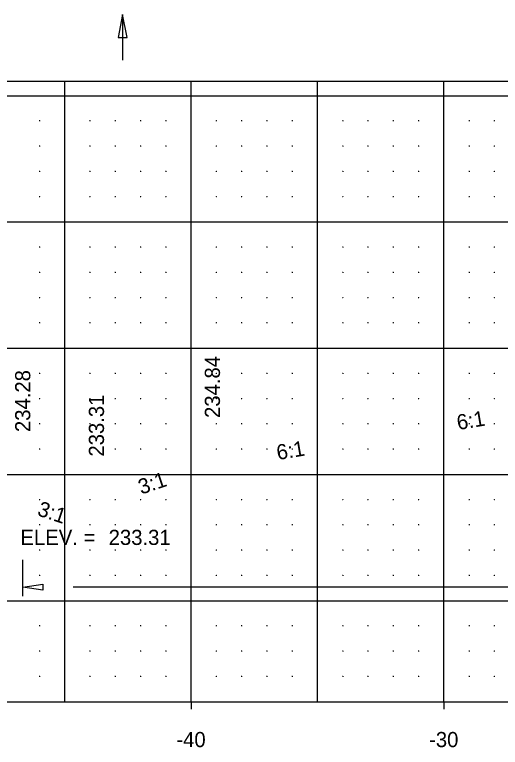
# Model space of a CAD drawing. Extents: x -80 to 80, y 222 to 253.
# Drawn here: x -46.98 to -27.76, y 224.19 to 253.21 of the extents above; entities that cross this region are included whole.
import ezdxf

# ---------------------------------------------------------------- set-up
doc = ezdxf.new("R2010")
doc.units = 0
for name, color, linetype in [('DSN_DRFT_XS Border Grid', 7, 'Continuous'), ('DSN_DRFT_XS Grid Annotations', 7, 'Continuous'), ('DSN_DRFT_XS Grid Major', 7, 'Continuous'), ('DSN_DRFT_XS Grid Minor', 7, 'Continuous'), ('DSN_DRFT_XS MOT STG Annotations', 7, 'Continuous'), ('DSN_RDWY_Flow Arrow', 7, 'Continuous'), ('DSN_RDWY_XS Annotation', 7, 'Continuous')]:
    doc.layers.add(name, color=color, linetype=linetype)

msp = doc.modelspace()

# ---------------------------------------------------------------- linework, layer by layer
at = {"layer": 'DSN_DRFT_XS Border Grid'}
for p, q in [((-77.5, 250.573), (77.5, 250.573)), ((-77.5, 226), (77.5, 226))]:
    msp.add_line(p, q, dxfattribs=at)
at = {"layer": 'DSN_DRFT_XS Grid Major'}
for p, q in [((-45, 226), (-45, 250.573)), ((-40, 226), (-40, 250.573)), ((-35, 226), (-35, 250.573)), ((-30, 226), (-30, 250.573)), ((-77.5, 250), (77.5, 250)), ((-77.5, 245), (77.5, 245)), ((-77.5, 240), (77.5, 240)), ((-77.5, 235), (77.5, 235)), ((-77.5, 230), (77.5, 230)), ((-40, 226), (-40, 225.7)), ((-30, 226), (-30, 225.7))]:
    msp.add_line(p, q, dxfattribs=at)
at = {"layer": 'DSN_DRFT_XS Grid Minor'}
for p, q in [((-45.988, 249), (-46.012, 249)), ((-46, 249.012), (-46, 248.988)), ((-43.988, 249), (-44.012, 249)), ((-44, 249.012), (-44, 248.988)), ((-42.988, 249), (-43.012, 249)), ((-43, 249.012), (-43, 248.988)), ((-41.988, 249), (-42.012, 249)), ((-42, 249.012), (-42, 248.988)), ((-40.988, 249), (-41.012, 249)), ((-41, 249.012), (-41, 248.988)), ((-38.988, 249), (-39.012, 249)), ((-39, 249.012), (-39, 248.988)), ((-37.988, 249), (-38.012, 249)), ((-38, 249.012), (-38, 248.988)), ((-36.988, 249), (-37.012, 249)), ((-37, 249.012), (-37, 248.988)), ((-35.988, 249), (-36.012, 249)), ((-36, 249.012), (-36, 248.988)), ((-33.988, 249), (-34.012, 249)), ((-34, 249.012), (-34, 248.988)), ((-32.988, 249), (-33.012, 249)), ((-33, 249.012), (-33, 248.988)), ((-31.988, 249), (-32.012, 249)), ((-32, 249.012), (-32, 248.988)), ((-30.988, 249), (-31.012, 249)), ((-31, 249.012), (-31, 248.988)), ((-28.988, 249), (-29.012, 249)), ((-29, 249.012), (-29, 248.988)), ((-27.988, 249), (-28.012, 249)), ((-28, 249.012), (-28, 248.988)), ((-45.988, 248), (-46.012, 248)), ((-46, 248.012), (-46, 247.988)), ((-43.988, 248), (-44.012, 248)), ((-44, 248.012), (-44, 247.988)), ((-42.988, 248), (-43.012, 248)), ((-43, 248.012), (-43, 247.988)), ((-41.988, 248), (-42.012, 248)), ((-42, 248.012), (-42, 247.988)), ((-40.988, 248), (-41.012, 248)), ((-41, 248.012), (-41, 247.988)), ((-38.988, 248), (-39.012, 248)), ((-39, 248.012), (-39, 247.988)), ((-37.988, 248), (-38.012, 248)), ((-38, 248.012), (-38, 247.988)), ((-36.988, 248), (-37.012, 248)), ((-37, 248.012), (-37, 247.988)), ((-35.988, 248), (-36.012, 248)), ((-36, 248.012), (-36, 247.988)), ((-33.988, 248), (-34.012, 248)), ((-34, 248.012), (-34, 247.988)), ((-32.988, 248), (-33.012, 248)), ((-33, 248.012), (-33, 247.988)), ((-31.988, 248), (-32.012, 248)), ((-32, 248.012), (-32, 247.988)), ((-30.988, 248), (-31.012, 248)), ((-31, 248.012), (-31, 247.988)), ((-28.988, 248), (-29.012, 248)), ((-29, 248.012), (-29, 247.988)), ((-27.988, 248), (-28.012, 248)), ((-28, 248.012), (-28, 247.988)), ((-45.988, 247), (-46.012, 247)), ((-46, 247.012), (-46, 246.988)), ((-43.988, 247), (-44.012, 247)), ((-44, 247.012), (-44, 246.988)), ((-42.988, 247), (-43.012, 247)), ((-43, 247.012), (-43, 246.988)), ((-41.988, 247), (-42.012, 247)), ((-42, 247.012), (-42, 246.988)), ((-40.988, 247), (-41.012, 247)), ((-41, 247.012), (-41, 246.988)), ((-38.988, 247), (-39.012, 247)), ((-39, 247.012), (-39, 246.988)), ((-37.988, 247), (-38.012, 247)), ((-38, 247.012), (-38, 246.988)), ((-36.988, 247), (-37.012, 247)), ((-37, 247.012), (-37, 246.988)), ((-35.988, 247), (-36.012, 247)), ((-36, 247.012), (-36, 246.988)), ((-33.988, 247), (-34.012, 247)), ((-34, 247.012), (-34, 246.988)), ((-32.988, 247), (-33.012, 247)), ((-33, 247.012), (-33, 246.988)), ((-31.988, 247), (-32.012, 247)), ((-32, 247.012), (-32, 246.988)), ((-30.988, 247), (-31.012, 247)), ((-31, 247.012), (-31, 246.988)), ((-28.988, 247), (-29.012, 247)), ((-29, 247.012), (-29, 246.988)), ((-27.988, 247), (-28.012, 247)), ((-28, 247.012), (-28, 246.988)), ((-45.988, 246), (-46.012, 246)), ((-46, 246.012), (-46, 245.988)), ((-43.988, 246), (-44.012, 246)), ((-44, 246.012), (-44, 245.988)), ((-42.988, 246), (-43.012, 246)), ((-43, 246.012), (-43, 245.988)), ((-41.988, 246), (-42.012, 246)), ((-42, 246.012), (-42, 245.988)), ((-40.988, 246), (-41.012, 246)), ((-41, 246.012), (-41, 245.988)), ((-38.988, 246), (-39.012, 246)), ((-39, 246.012), (-39, 245.988)), ((-37.988, 246), (-38.012, 246)), ((-38, 246.012), (-38, 245.988)), ((-36.988, 246), (-37.012, 246)), ((-37, 246.012), (-37, 245.988)), ((-35.988, 246), (-36.012, 246)), ((-36, 246.012), (-36, 245.988)), ((-33.988, 246), (-34.012, 246)), ((-34, 246.012), (-34, 245.988)), ((-32.988, 246), (-33.012, 246)), ((-33, 246.012), (-33, 245.988)), ((-31.988, 246), (-32.012, 246)), ((-32, 246.012), (-32, 245.988)), ((-30.988, 246), (-31.012, 246)), ((-31, 246.012), (-31, 245.988)), ((-28.988, 246), (-29.012, 246)), ((-29, 246.012), (-29, 245.988)), ((-27.988, 246), (-28.012, 246)), ((-28, 246.012), (-28, 245.988)), ((-45.988, 244), (-46.012, 244)), ((-46, 244.012), (-46, 243.988)), ((-43.988, 244), (-44.012, 244)), ((-44, 244.012), (-44, 243.988)), ((-42.988, 244), (-43.012, 244)), ((-43, 244.012), (-43, 243.988)), ((-41.988, 244), (-42.012, 244)), ((-42, 244.012), (-42, 243.988)), ((-40.988, 244), (-41.012, 244)), ((-41, 244.012), (-41, 243.988)), ((-38.988, 244), (-39.012, 244)), ((-39, 244.012), (-39, 243.988)), ((-37.988, 244), (-38.012, 244)), ((-38, 244.012), (-38, 243.988)), ((-36.988, 244), (-37.012, 244)), ((-37, 244.012), (-37, 243.988)), ((-35.988, 244), (-36.012, 244)), ((-36, 244.012), (-36, 243.988)), ((-33.988, 244), (-34.012, 244)), ((-34, 244.012), (-34, 243.988)), ((-32.988, 244), (-33.012, 244)), ((-33, 244.012), (-33, 243.988)), ((-31.988, 244), (-32.012, 244)), ((-32, 244.012), (-32, 243.988)), ((-30.988, 244), (-31.012, 244)), ((-31, 244.012), (-31, 243.988)), ((-28.988, 244), (-29.012, 244)), ((-29, 244.012), (-29, 243.988)), ((-27.988, 244), (-28.012, 244)), ((-28, 244.012), (-28, 243.988)), ((-45.988, 243), (-46.012, 243)), ((-46, 243.012), (-46, 242.988)), ((-43.988, 243), (-44.012, 243)), ((-44, 243.012), (-44, 242.988)), ((-42.988, 243), (-43.012, 243)), ((-43, 243.012), (-43, 242.988)), ((-41.988, 243), (-42.012, 243)), ((-42, 243.012), (-42, 242.988)), ((-40.988, 243), (-41.012, 243)), ((-41, 243.012), (-41, 242.988)), ((-38.988, 243), (-39.012, 243)), ((-39, 243.012), (-39, 242.988)), ((-37.988, 243), (-38.012, 243)), ((-38, 243.012), (-38, 242.988)), ((-36.988, 243), (-37.012, 243)), ((-37, 243.012), (-37, 242.988)), ((-35.988, 243), (-36.012, 243)), ((-36, 243.012), (-36, 242.988)), ((-33.988, 243), (-34.012, 243)), ((-34, 243.012), (-34, 242.988)), ((-32.988, 243), (-33.012, 243)), ((-33, 243.012), (-33, 242.988)), ((-31.988, 243), (-32.012, 243)), ((-32, 243.012), (-32, 242.988)), ((-30.988, 243), (-31.012, 243)), ((-31, 243.012), (-31, 242.988)), ((-28.988, 243), (-29.012, 243)), ((-29, 243.012), (-29, 242.988)), ((-27.988, 243), (-28.012, 243)), ((-28, 243.012), (-28, 242.988)), ((-46, 242.012), (-46, 241.988)), ((-44, 242.012), (-44, 241.988)), ((-43, 242.012), (-43, 241.988)), ((-42, 242.012), (-42, 241.988)), ((-41, 242.012), (-41, 241.988)), ((-39, 242.012), (-39, 241.988)), ((-38, 242.012), (-38, 241.988)), ((-37, 242.012), (-37, 241.988)), ((-36, 242.012), (-36, 241.988)), ((-34, 242.012), (-34, 241.988)), ((-33, 242.012), (-33, 241.988)), ((-32, 242.012), (-32, 241.988)), ((-31, 242.012), (-31, 241.988)), ((-29, 242.012), (-29, 241.988)), ((-28, 242.012), (-28, 241.988)), ((-45.988, 242), (-46.012, 242)), ((-43.988, 242), (-44.012, 242)), ((-42.988, 242), (-43.012, 242)), ((-41.988, 242), (-42.012, 242)), ((-40.988, 242), (-41.012, 242)), ((-38.988, 242), (-39.012, 242)), ((-37.988, 242), (-38.012, 242)), ((-36.988, 242), (-37.012, 242)), ((-35.988, 242), (-36.012, 242)), ((-33.988, 242), (-34.012, 242)), ((-32.988, 242), (-33.012, 242)), ((-31.988, 242), (-32.012, 242)), ((-30.988, 242), (-31.012, 242)), ((-28.988, 242), (-29.012, 242)), ((-27.988, 242), (-28.012, 242)), ((-45.988, 241), (-46.012, 241)), ((-46, 241.012), (-46, 240.988)), ((-43.988, 241), (-44.012, 241)), ((-44, 241.012), (-44, 240.988)), ((-42.988, 241), (-43.012, 241)), ((-43, 241.012), (-43, 240.988)), ((-41.988, 241), (-42.012, 241)), ((-42, 241.012), (-42, 240.988)), ((-40.988, 241), (-41.012, 241)), ((-41, 241.012), (-41, 240.988)), ((-38.988, 241), (-39.012, 241)), ((-39, 241.012), (-39, 240.988)), ((-37.988, 241), (-38.012, 241)), ((-38, 241.012), (-38, 240.988)), ((-36.988, 241), (-37.012, 241)), ((-37, 241.012), (-37, 240.988)), ((-35.988, 241), (-36.012, 241)), ((-36, 241.012), (-36, 240.988)), ((-33.988, 241), (-34.012, 241)), ((-34, 241.012), (-34, 240.988)), ((-32.988, 241), (-33.012, 241)), ((-33, 241.012), (-33, 240.988)), ((-31.988, 241), (-32.012, 241)), ((-32, 241.012), (-32, 240.988)), ((-30.988, 241), (-31.012, 241)), ((-31, 241.012), (-31, 240.988)), ((-28.988, 241), (-29.012, 241)), ((-29, 241.012), (-29, 240.988)), ((-27.988, 241), (-28.012, 241)), ((-28, 241.012), (-28, 240.988)), ((-45.988, 239), (-46.012, 239)), ((-46, 239.012), (-46, 238.988)), ((-43.988, 239), (-44.012, 239)), ((-44, 239.012), (-44, 238.988)), ((-42.988, 239), (-43.012, 239)), ((-43, 239.012), (-43, 238.988)), ((-41.988, 239), (-42.012, 239)), ((-42, 239.012), (-42, 238.988)), ((-40.988, 239), (-41.012, 239)), ((-41, 239.012), (-41, 238.988)), ((-38.988, 239), (-39.012, 239)), ((-39, 239.012), (-39, 238.988)), ((-37.988, 239), (-38.012, 239)), ((-38, 239.012), (-38, 238.988)), ((-36.988, 239), (-37.012, 239)), ((-37, 239.012), (-37, 238.988)), ((-35.988, 239), (-36.012, 239)), ((-36, 239.012), (-36, 238.988)), ((-33.988, 239), (-34.012, 239)), ((-34, 239.012), (-34, 238.988)), ((-32.988, 239), (-33.012, 239)), ((-33, 239.012), (-33, 238.988)), ((-31.988, 239), (-32.012, 239)), ((-32, 239.012), (-32, 238.988)), ((-30.988, 239), (-31.012, 239)), ((-31, 239.012), (-31, 238.988)), ((-28.988, 239), (-29.012, 239)), ((-29, 239.012), (-29, 238.988)), ((-27.988, 239), (-28.012, 239)), ((-28, 239.012), (-28, 238.988)), ((-45.988, 238), (-46.012, 238)), ((-46, 238.012), (-46, 237.988)), ((-43.988, 238), (-44.012, 238)), ((-44, 238.012), (-44, 237.988)), ((-42.988, 238), (-43.012, 238)), ((-43, 238.012), (-43, 237.988)), ((-41.988, 238), (-42.012, 238)), ((-42, 238.012), (-42, 237.988)), ((-40.988, 238), (-41.012, 238)), ((-41, 238.012), (-41, 237.988)), ((-38.988, 238), (-39.012, 238)), ((-39, 238.012), (-39, 237.988)), ((-37.988, 238), (-38.012, 238)), ((-38, 238.012), (-38, 237.988)), ((-36.988, 238), (-37.012, 238)), ((-37, 238.012), (-37, 237.988)), ((-35.988, 238), (-36.012, 238)), ((-36, 238.012), (-36, 237.988)), ((-33.988, 238), (-34.012, 238)), ((-34, 238.012), (-34, 237.988)), ((-32.988, 238), (-33.012, 238)), ((-33, 238.012), (-33, 237.988)), ((-31.988, 238), (-32.012, 238)), ((-32, 238.012), (-32, 237.988)), ((-30.988, 238), (-31.012, 238)), ((-31, 238.012), (-31, 237.988)), ((-28.988, 238), (-29.012, 238)), ((-29, 238.012), (-29, 237.988)), ((-27.988, 238), (-28.012, 238)), ((-28, 238.012), (-28, 237.988)), ((-45.988, 237), (-46.012, 237)), ((-46, 237.012), (-46, 236.988)), ((-43.988, 237), (-44.012, 237)), ((-44, 237.012), (-44, 236.988)), ((-42.988, 237), (-43.012, 237)), ((-43, 237.012), (-43, 236.988)), ((-41.988, 237), (-42.012, 237)), ((-42, 237.012), (-42, 236.988)), ((-40.988, 237), (-41.012, 237)), ((-41, 237.012), (-41, 236.988)), ((-38.988, 237), (-39.012, 237)), ((-39, 237.012), (-39, 236.988)), ((-37.988, 237), (-38.012, 237)), ((-38, 237.012), (-38, 236.988)), ((-36.988, 237), (-37.012, 237)), ((-37, 237.012), (-37, 236.988)), ((-35.988, 237), (-36.012, 237)), ((-36, 237.012), (-36, 236.988)), ((-33.988, 237), (-34.012, 237)), ((-34, 237.012), (-34, 236.988)), ((-32.988, 237), (-33.012, 237)), ((-33, 237.012), (-33, 236.988)), ((-31.988, 237), (-32.012, 237)), ((-32, 237.012), (-32, 236.988)), ((-30.988, 237), (-31.012, 237)), ((-31, 237.012), (-31, 236.988)), ((-28.988, 237), (-29.012, 237)), ((-29, 237.012), (-29, 236.988)), ((-27.988, 237), (-28.012, 237)), ((-28, 237.012), (-28, 236.988)), ((-45.988, 236), (-46.012, 236)), ((-46, 236.012), (-46, 235.988)), ((-43.988, 236), (-44.012, 236)), ((-44, 236.012), (-44, 235.988)), ((-42.988, 236), (-43.012, 236)), ((-43, 236.012), (-43, 235.988)), ((-41.988, 236), (-42.012, 236)), ((-42, 236.012), (-42, 235.988)), ((-40.988, 236), (-41.012, 236)), ((-41, 236.012), (-41, 235.988)), ((-38.988, 236), (-39.012, 236)), ((-39, 236.012), (-39, 235.988)), ((-37.988, 236), (-38.012, 236)), ((-38, 236.012), (-38, 235.988)), ((-36.988, 236), (-37.012, 236)), ((-37, 236.012), (-37, 235.988)), ((-35.988, 236), (-36.012, 236)), ((-36, 236.012), (-36, 235.988)), ((-33.988, 236), (-34.012, 236)), ((-34, 236.012), (-34, 235.988)), ((-32.988, 236), (-33.012, 236)), ((-33, 236.012), (-33, 235.988)), ((-31.988, 236), (-32.012, 236)), ((-32, 236.012), (-32, 235.988)), ((-30.988, 236), (-31.012, 236)), ((-31, 236.012), (-31, 235.988)), ((-28.988, 236), (-29.012, 236)), ((-29, 236.012), (-29, 235.988)), ((-27.988, 236), (-28.012, 236)), ((-28, 236.012), (-28, 235.988)), ((-45.988, 234), (-46.012, 234)), ((-46, 234.012), (-46, 233.988)), ((-43.988, 234), (-44.012, 234)), ((-44, 234.012), (-44, 233.988)), ((-42.988, 234), (-43.012, 234)), ((-43, 234.012), (-43, 233.988)), ((-41.988, 234), (-42.012, 234)), ((-42, 234.012), (-42, 233.988)), ((-40.988, 234), (-41.012, 234)), ((-41, 234.012), (-41, 233.988)), ((-38.988, 234), (-39.012, 234)), ((-39, 234.012), (-39, 233.988)), ((-37.988, 234), (-38.012, 234)), ((-38, 234.012), (-38, 233.988)), ((-36.988, 234), (-37.012, 234)), ((-37, 234.012), (-37, 233.988)), ((-35.988, 234), (-36.012, 234)), ((-36, 234.012), (-36, 233.988)), ((-33.988, 234), (-34.012, 234)), ((-34, 234.012), (-34, 233.988)), ((-32.988, 234), (-33.012, 234)), ((-33, 234.012), (-33, 233.988)), ((-31.988, 234), (-32.012, 234)), ((-32, 234.012), (-32, 233.988)), ((-30.988, 234), (-31.012, 234)), ((-31, 234.012), (-31, 233.988)), ((-28.988, 234), (-29.012, 234)), ((-29, 234.012), (-29, 233.988)), ((-27.988, 234), (-28.012, 234)), ((-28, 234.012), (-28, 233.988)), ((-46, 233.012), (-46, 232.988)), ((-44, 233.012), (-44, 232.988)), ((-43, 233.012), (-43, 232.988)), ((-42, 233.012), (-42, 232.988)), ((-41, 233.012), (-41, 232.988)), ((-39, 233.012), (-39, 232.988)), ((-38, 233.012), (-38, 232.988)), ((-37, 233.012), (-37, 232.988)), ((-36, 233.012), (-36, 232.988)), ((-34, 233.012), (-34, 232.988)), ((-33, 233.012), (-33, 232.988)), ((-32, 233.012), (-32, 232.988)), ((-31, 233.012), (-31, 232.988)), ((-29, 233.012), (-29, 232.988)), ((-28, 233.012), (-28, 232.988)), ((-45.988, 233), (-46.012, 233)), ((-43.988, 233), (-44.012, 233)), ((-42.988, 233), (-43.012, 233)), ((-41.988, 233), (-42.012, 233)), ((-40.988, 233), (-41.012, 233)), ((-38.988, 233), (-39.012, 233)), ((-37.988, 233), (-38.012, 233)), ((-36.988, 233), (-37.012, 233)), ((-35.988, 233), (-36.012, 233)), ((-33.988, 233), (-34.012, 233)), ((-32.988, 233), (-33.012, 233)), ((-31.988, 233), (-32.012, 233)), ((-30.988, 233), (-31.012, 233)), ((-28.988, 233), (-29.012, 233)), ((-27.988, 233), (-28.012, 233)), ((-45.988, 232), (-46.012, 232)), ((-46, 232.012), (-46, 231.988)), ((-43.988, 232), (-44.012, 232)), ((-44, 232.012), (-44, 231.988)), ((-42.988, 232), (-43.012, 232)), ((-43, 232.012), (-43, 231.988)), ((-41.988, 232), (-42.012, 232)), ((-42, 232.012), (-42, 231.988)), ((-40.988, 232), (-41.012, 232)), ((-41, 232.012), (-41, 231.988)), ((-38.988, 232), (-39.012, 232)), ((-39, 232.012), (-39, 231.988)), ((-37.988, 232), (-38.012, 232)), ((-38, 232.012), (-38, 231.988)), ((-36.988, 232), (-37.012, 232)), ((-37, 232.012), (-37, 231.988)), ((-35.988, 232), (-36.012, 232)), ((-36, 232.012), (-36, 231.988)), ((-33.988, 232), (-34.012, 232)), ((-34, 232.012), (-34, 231.988)), ((-32.988, 232), (-33.012, 232)), ((-33, 232.012), (-33, 231.988)), ((-31.988, 232), (-32.012, 232)), ((-32, 232.012), (-32, 231.988)), ((-30.988, 232), (-31.012, 232)), ((-31, 232.012), (-31, 231.988)), ((-28.988, 232), (-29.012, 232)), ((-29, 232.012), (-29, 231.988)), ((-27.988, 232), (-28.012, 232)), ((-28, 232.012), (-28, 231.988)), ((-45.988, 231), (-46.012, 231)), ((-46, 231.012), (-46, 230.988)), ((-43.988, 231), (-44.012, 231)), ((-44, 231.012), (-44, 230.988)), ((-42.988, 231), (-43.012, 231)), ((-43, 231.012), (-43, 230.988)), ((-41.988, 231), (-42.012, 231)), ((-42, 231.012), (-42, 230.988)), ((-40.988, 231), (-41.012, 231)), ((-41, 231.012), (-41, 230.988)), ((-38.988, 231), (-39.012, 231)), ((-39, 231.012), (-39, 230.988)), ((-37.988, 231), (-38.012, 231)), ((-38, 231.012), (-38, 230.988)), ((-36.988, 231), (-37.012, 231)), ((-37, 231.012), (-37, 230.988)), ((-35.988, 231), (-36.012, 231)), ((-36, 231.012), (-36, 230.988)), ((-33.988, 231), (-34.012, 231)), ((-34, 231.012), (-34, 230.988)), ((-32.988, 231), (-33.012, 231)), ((-33, 231.012), (-33, 230.988)), ((-31.988, 231), (-32.012, 231)), ((-32, 231.012), (-32, 230.988)), ((-30.988, 231), (-31.012, 231)), ((-31, 231.012), (-31, 230.988)), ((-28.988, 231), (-29.012, 231)), ((-29, 231.012), (-29, 230.988)), ((-27.988, 231), (-28.012, 231)), ((-28, 231.012), (-28, 230.988)), ((-45.988, 229), (-46.012, 229)), ((-46, 229.012), (-46, 228.988)), ((-43.988, 229), (-44.012, 229)), ((-44, 229.012), (-44, 228.988)), ((-42.988, 229), (-43.012, 229)), ((-43, 229.012), (-43, 228.988)), ((-41.988, 229), (-42.012, 229)), ((-42, 229.012), (-42, 228.988)), ((-40.988, 229), (-41.012, 229)), ((-41, 229.012), (-41, 228.988)), ((-38.988, 229), (-39.012, 229)), ((-39, 229.012), (-39, 228.988)), ((-37.988, 229), (-38.012, 229)), ((-38, 229.012), (-38, 228.988)), ((-36.988, 229), (-37.012, 229)), ((-37, 229.012), (-37, 228.988)), ((-35.988, 229), (-36.012, 229)), ((-36, 229.012), (-36, 228.988)), ((-33.988, 229), (-34.012, 229)), ((-34, 229.012), (-34, 228.988)), ((-32.988, 229), (-33.012, 229)), ((-33, 229.012), (-33, 228.988)), ((-31.988, 229), (-32.012, 229)), ((-32, 229.012), (-32, 228.988)), ((-30.988, 229), (-31.012, 229)), ((-31, 229.012), (-31, 228.988)), ((-28.988, 229), (-29.012, 229)), ((-29, 229.012), (-29, 228.988)), ((-27.988, 229), (-28.012, 229)), ((-28, 229.012), (-28, 228.988)), ((-45.988, 228), (-46.012, 228)), ((-46, 228.012), (-46, 227.988)), ((-43.988, 228), (-44.012, 228)), ((-44, 228.012), (-44, 227.988)), ((-42.988, 228), (-43.012, 228)), ((-43, 228.012), (-43, 227.988)), ((-41.988, 228), (-42.012, 228)), ((-42, 228.012), (-42, 227.988)), ((-40.988, 228), (-41.012, 228)), ((-41, 228.012), (-41, 227.988)), ((-38.988, 228), (-39.012, 228)), ((-39, 228.012), (-39, 227.988)), ((-37.988, 228), (-38.012, 228)), ((-38, 228.012), (-38, 227.988)), ((-36.988, 228), (-37.012, 228)), ((-37, 228.012), (-37, 227.988)), ((-35.988, 228), (-36.012, 228)), ((-36, 228.012), (-36, 227.988)), ((-33.988, 228), (-34.012, 228)), ((-34, 228.012), (-34, 227.988)), ((-32.988, 228), (-33.012, 228)), ((-33, 228.012), (-33, 227.988)), ((-31.988, 228), (-32.012, 228)), ((-32, 228.012), (-32, 227.988)), ((-30.988, 228), (-31.012, 228)), ((-31, 228.012), (-31, 227.988)), ((-28.988, 228), (-29.012, 228)), ((-29, 228.012), (-29, 227.988)), ((-27.988, 228), (-28.012, 228)), ((-28, 228.012), (-28, 227.988)), ((-45.988, 227), (-46.012, 227)), ((-46, 227.012), (-46, 226.988)), ((-43.988, 227), (-44.012, 227)), ((-44, 227.012), (-44, 226.988)), ((-42.988, 227), (-43.012, 227)), ((-43, 227.012), (-43, 226.988)), ((-41.988, 227), (-42.012, 227)), ((-42, 227.012), (-42, 226.988)), ((-40.988, 227), (-41.012, 227)), ((-41, 227.012), (-41, 226.988)), ((-38.988, 227), (-39.012, 227)), ((-39, 227.012), (-39, 226.988)), ((-37.988, 227), (-38.012, 227)), ((-38, 227.012), (-38, 226.988)), ((-36.988, 227), (-37.012, 227)), ((-37, 227.012), (-37, 226.988)), ((-35.988, 227), (-36.012, 227)), ((-36, 227.012), (-36, 226.988)), ((-33.988, 227), (-34.012, 227)), ((-34, 227.012), (-34, 226.988)), ((-32.988, 227), (-33.012, 227)), ((-33, 227.012), (-33, 226.988)), ((-31.988, 227), (-32.012, 227)), ((-32, 227.012), (-32, 226.988)), ((-30.988, 227), (-31.012, 227)), ((-31, 227.012), (-31, 226.988)), ((-28.988, 227), (-29.012, 227)), ((-29, 227.012), (-29, 226.988)), ((-27.988, 227), (-28.012, 227)), ((-28, 227.012), (-28, 226.988))]:
    msp.add_line(p, q, dxfattribs=at)
at = {"layer": 'DSN_DRFT_XS MOT STG Annotations'}
for p, q in [((-46.66, 230.178), (-46.66, 231.618)), ((-44.67, 230.544), (-12.416, 230.544))]:
    msp.add_line(p, q, dxfattribs=at)
msp.add_lwpolyline([(-45.86, 230.418), (-46.66, 230.538), (-45.86, 230.658)], close=True, dxfattribs=at)
at = {"layer": 'DSN_RDWY_Flow Arrow'}
msp.add_lwpolyline([(-42.708, 253.209), (-42.888, 252.309), (-42.528, 252.309), (-42.708, 253.209), (-42.708, 251.409)], dxfattribs=at)

# ---------------------------------------------------------------- texts
at = {"layer": 'DSN_DRFT_XS Grid Annotations'}
for s, p in [('-40', (-40.581, 224.2)), ('-30', (-30.581, 224.2))]:
    msp.add_text(s, height=0.6, dxfattribs=at).set_placement(p)
at = {"layer": 'DSN_RDWY_XS Annotation'}
for s, rotation, p in [('234.84', 90, (-38.855, 237.237)), ('234.28', 90, (-46.36, 236.679)), ('233.31', 90, (-43.444, 235.707)), ('6:1', 9.4623, (-29.433, 236.757)), ('6:1', 9.4623, (-36.566, 235.568)), ('3:1', 18.4349, (-41.971, 234.198)), ('3:1', 341.5651, (-46.12, 233.39))]:
    msp.add_text(s, height=0.6, rotation=rotation, dxfattribs=at).set_placement(p)
for s, p in [('ELEV. = ', (-46.751, 232.207)), ('233.31', (-43.26, 232.207))]:
    msp.add_text(s, height=0.6, dxfattribs=at).set_placement(p)

doc.saveas('drawing.dxf')
